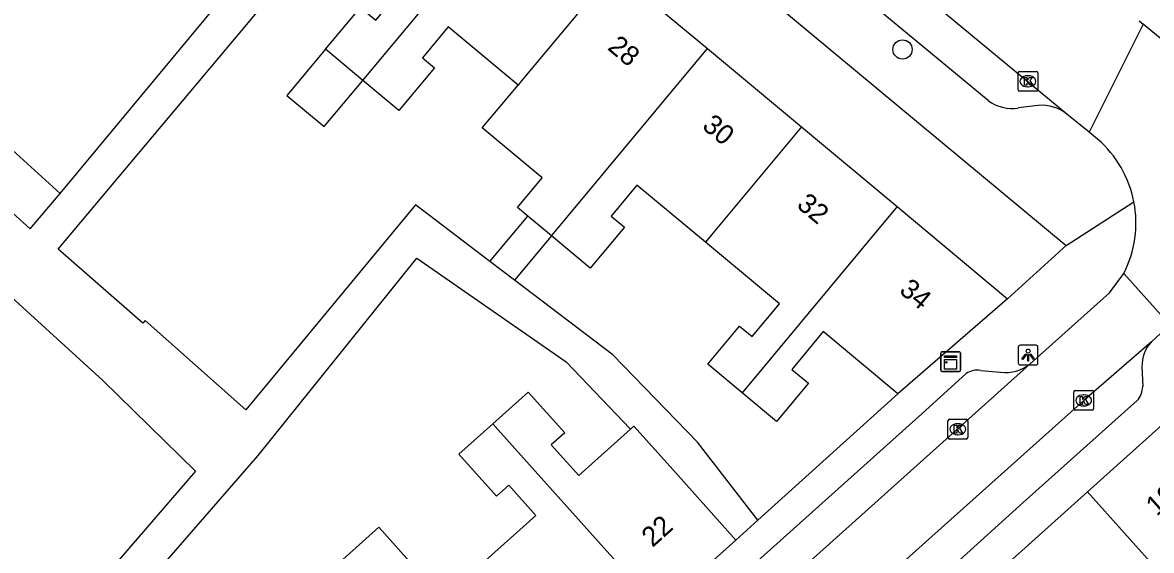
# Model space of a CAD drawing. Extents: x 158352 to 159489, y 383828 to 384597.
# Drawn here: x 159153.3 to 159210.4, y 384287.6 to 384314.3 of the extents above; entities that cross this region are included whole.
import ezdxf

# ---------------------------------------------------------------- set-up
doc = ezdxf.new("R2010")
doc.units = 0
for name, color, linetype in [('IMGEO_Boom', 7, 'Continuous'), ('IMGEO_Kast', 7, 'Continuous'), ('IMGEO_Kolk', 7, 'Continuous'), ('IMGEO_Lichtpunt', 7, 'Continuous'), ('IMGEO_Muur', 7, 'Continuous'), ('IMGEO_Pand', 7, 'Continuous'), ('IMGEO_Pand_nummerreeks', 7, 'Continuous'), ('IMGEO_Rijbaan_lokaal_open', 7, 'Continuous'), ('IMGEO_Voetpad_open', 7, 'Continuous')]:
    doc.layers.add(name, color=color, linetype=linetype)

msp = doc.modelspace()

# ---------------------------------------------------------------- linework, layer by layer
at = {"layer": 'IMGEO_Boom'}
msp.add_circle((159197.826, 384312.907), 0.489, dxfattribs=at)
at = {"layer": 'IMGEO_Kast'}
for p, q in [((159199.759, 384296.687), (159199.759, 384297.528)), ((159199.759, 384297.528), (159199.759, 384296.687)), ((159199.834, 384297.612), (159200.675, 384297.612)), ((159200.675, 384297.612), (159199.834, 384297.612)), ((159200.759, 384297.537), (159200.759, 384296.696)), ((159200.759, 384296.696), (159200.759, 384297.537)), ((159200.684, 384296.612), (159199.843, 384296.612)), ((159199.843, 384296.612), (159200.684, 384296.612))]:
    msp.add_line(p, q, dxfattribs=at)
for points in [[(159199.954, 384297.402), (159200.554, 384297.402), (159200.554, 384297.317), (159199.954, 384297.317), (159199.954, 384297.402)], [(159199.954, 384297.227), (159200.554, 384297.227), (159200.554, 384296.738), (159199.954, 384296.738), (159199.954, 384297.227)]]:
    msp.add_lwpolyline(points, dxfattribs=at)
msp.add_circle((159200.038, 384297.076), 0.0377, dxfattribs=at)
for centre, start, end in [((159199.837, 384297.534), 92.4484, 184.2845), ((159199.837, 384297.534), 92.4484, 184.2845), ((159200.681, 384297.534), 2.4484, 94.2845), ((159200.681, 384297.534), 2.4484, 94.2845), ((159199.837, 384296.69), 182.4484, 274.2845), ((159199.837, 384296.69), 182.4484, 274.2845), ((159200.681, 384296.69), 272.4484, 4.2845), ((159200.681, 384296.69), 272.4484, 4.2845)]:
    msp.add_arc(centre, 0.0779, start, end, dxfattribs=at)
at = {"layer": 'IMGEO_Kolk'}
for p, q in [((159203.67, 384310.871), (159203.67, 384311.723)), ((159203.745, 384311.797), (159204.597, 384311.797)), ((159204.158, 384311.577), (159204.183, 384311.577)), ((159204.671, 384311.723), (159204.671, 384310.871)), ((159204.181, 384311.017), (159204.156, 384311.017)), ((159204.597, 384310.797), (159203.745, 384310.797)), ((159206.492, 384294.726), (159206.492, 384295.578)), ((159206.567, 384295.652), (159207.419, 384295.652)), ((159207.493, 384295.578), (159207.493, 384294.726)), ((159206.98, 384295.432), (159207.005, 384295.432)), ((159207.419, 384294.652), (159206.567, 384294.652)), ((159207.003, 384294.872), (159206.978, 384294.872)), ((159200.122, 384293.269), (159200.122, 384294.121)), ((159200.197, 384294.195), (159201.049, 384294.195)), ((159200.61, 384293.975), (159200.635, 384293.975)), ((159201.123, 384294.121), (159201.123, 384293.269)), ((159201.049, 384293.195), (159200.197, 384293.195)), ((159200.633, 384293.415), (159200.608, 384293.415))]:
    msp.add_line(p, q, dxfattribs=at)
for points in [[(159203.67, 384310.871), (159203.67, 384311.723)], [(159203.745, 384311.797), (159204.597, 384311.797)], [(159203.991, 384311.497), (159204.114, 384311.497), (159204.114, 384311.346), (159204.244, 384311.497), (159204.408, 384311.497), (159204.262, 384311.346), (159204.415, 384311.097), (159204.263, 384311.097), (159204.178, 384311.261), (159204.114, 384311.194), (159204.114, 384311.097), (159203.991, 384311.097), (159203.991, 384311.497)], [(159204.671, 384311.723), (159204.671, 384310.871)], [(159204.597, 384310.797), (159203.745, 384310.797)], [(159206.492, 384294.726), (159206.492, 384295.578)], [(159206.567, 384295.652), (159207.419, 384295.652)], [(159207.493, 384295.578), (159207.493, 384294.726)], [(159206.813, 384295.352), (159206.936, 384295.352), (159206.936, 384295.201), (159207.066, 384295.352), (159207.23, 384295.352), (159207.084, 384295.201), (159207.237, 384294.952), (159207.085, 384294.952), (159207, 384295.116), (159206.936, 384295.049), (159206.936, 384294.952), (159206.813, 384294.952), (159206.813, 384295.352)], [(159207.419, 384294.652), (159206.567, 384294.652)], [(159200.122, 384293.269), (159200.122, 384294.121)], [(159200.197, 384294.195), (159201.049, 384294.195)], [(159200.443, 384293.895), (159200.566, 384293.895), (159200.566, 384293.744), (159200.696, 384293.895), (159200.86, 384293.895), (159200.714, 384293.744), (159200.867, 384293.495), (159200.715, 384293.495), (159200.63, 384293.659), (159200.566, 384293.592), (159200.566, 384293.495), (159200.443, 384293.495), (159200.443, 384293.895)], [(159201.123, 384294.121), (159201.123, 384293.269)], [(159201.049, 384293.195), (159200.197, 384293.195)]]:
    msp.add_lwpolyline(points, dxfattribs=at)
for centre, start, end in [((159203.747, 384311.721), 91.552, 178.448), ((159203.747, 384311.721), 91.552, 178.448), ((159204.595, 384311.721), 1.552, 88.448), ((159204.595, 384311.721), 1.552, 88.448), ((159203.747, 384310.873), 181.552, 268.448), ((159203.747, 384310.873), 181.552, 268.448), ((159204.595, 384310.873), 271.552, 358.448), ((159204.595, 384310.873), 271.552, 358.448), ((159206.569, 384295.576), 91.552, 178.448), ((159206.569, 384295.576), 91.552, 178.448), ((159207.417, 384295.576), 1.552, 88.448), ((159207.417, 384295.576), 1.552, 88.448), ((159206.569, 384294.728), 181.552, 268.448), ((159206.569, 384294.728), 181.552, 268.448), ((159207.417, 384294.728), 271.552, 358.448), ((159207.417, 384294.728), 271.552, 358.448), ((159200.199, 384294.119), 91.552, 178.448), ((159200.199, 384294.119), 91.552, 178.448), ((159201.047, 384294.119), 1.552, 88.448), ((159201.047, 384294.119), 1.552, 88.448), ((159200.199, 384293.271), 181.552, 268.448), ((159200.199, 384293.271), 181.552, 268.448), ((159201.047, 384293.271), 271.552, 358.448), ((159201.047, 384293.271), 271.552, 358.448)]:
    msp.add_arc(centre, 0.0765, start, end, dxfattribs=at)
for centre, major_axis, ratio, start_param, end_param in [((159204.157, 384311.297), (-0.387, 0.002), 0.722429, 4.712389, 7.853982), ((159204.182, 384311.297), (-0.39, 0.002), 0.717154, 1.570796, 4.712389), ((159206.979, 384295.152), (-0.387, 0.002), 0.722429, 4.712389, 7.853982), ((159207.004, 384295.152), (-0.39, 0.002), 0.717154, 1.570796, 4.712389), ((159200.609, 384293.695), (-0.387, 0.002), 0.722429, 4.712389, 7.853982), ((159200.634, 384293.695), (-0.39, 0.002), 0.717154, 1.570796, 4.712389)]:
    msp.add_ellipse(centre, major_axis=major_axis, ratio=ratio, start_param=start_param, end_param=end_param, dxfattribs=at)
at = {"layer": 'IMGEO_Lichtpunt'}
for p, q in [((159203.684, 384297.851), (159203.684, 384297.044)), ((159203.684, 384297.851), (159203.684, 384297.044)), ((159204.586, 384297.946), (159203.778, 384297.946)), ((159204.586, 384297.946), (159203.778, 384297.946)), ((159204.68, 384297.044), (159204.68, 384297.851)), ((159204.68, 384297.044), (159204.68, 384297.851)), ((159203.778, 384296.95), (159204.586, 384296.95)), ((159203.778, 384296.95), (159204.586, 384296.95))]:
    msp.add_line(p, q, dxfattribs=at)
for points in [[(159204.058, 384297.515), (159204.097, 384297.487), (159203.909, 384297.225), (159203.871, 384297.252), (159204.058, 384297.515)], [(159204.16, 384297.467), (159204.207, 384297.467), (159204.207, 384297.145), (159204.16, 384297.145), (159204.16, 384297.467)], [(159204.27, 384297.487), (159204.308, 384297.514), (159204.495, 384297.252), (159204.456, 384297.224), (159204.27, 384297.487)]]:
    msp.add_lwpolyline(points, dxfattribs=at)
msp.add_circle((159204.183, 384297.649), 0.0994, dxfattribs=at)
for centre, start, end in [((159203.778, 384297.851), 90, 180), ((159203.778, 384297.851), 90, 180), ((159204.586, 384297.851), 0, 90), ((159204.586, 384297.851), 0, 90), ((159203.778, 384297.044), 180, 270), ((159203.778, 384297.044), 180, 270), ((159204.586, 384297.044), 270, 0), ((159204.586, 384297.044), 270, 360)]:
    msp.add_arc(centre, 0.0946, start, end, dxfattribs=at)
at = {"layer": 'IMGEO_Muur'}
msp.add_lwpolyline([(159190.512, 384289.089), (159197.594, 384295.481)], dxfattribs=at)
at = {"layer": 'IMGEO_Pand'}
for points in [[(159170.516, 384311.346), (159170.584, 384311.428), (159178.46, 384320.872)], [(159168.63, 384312.919), (159170.397, 384315.039), (159171.182, 384314.384), (159172.535, 384316.006), (159168.795, 384319.124)], [(159183.209, 384316.912), (159178.531, 384311.302), (159178.37, 384311.109)], [(159183.209, 384316.912), (159187.959, 384312.952)], [(159178.37, 384311.109), (159174.841, 384314.052), (159173.529, 384312.479), (159174.137, 384311.972), (159172.344, 384309.822), (159170.516, 384311.346)], [(159168.63, 384312.919), (159166.676, 384310.574), (159168.554, 384309.008), (159170.516, 384311.346)], [(159170.516, 384311.346), (159168.63, 384312.919)], [(159180.057, 384303.476), (159180.158, 384303.598), (159187.959, 384312.952)], [(159187.959, 384312.952), (159192.708, 384308.992)], [(159178.858, 384304.475), (159178.343, 384304.905), (159179.599, 384306.411), (159176.563, 384308.942), (159178.37, 384311.109)], [(159155.206, 384305.626), (159150.73, 384309.667), (159149.226, 384307.855)], [(159192.708, 384308.992), (159188.159, 384303.537), (159187.848, 384303.164)], [(159192.708, 384308.992), (159197.549, 384304.956)], [(159149.226, 384307.855), (159153.686, 384303.826), (159155.206, 384305.626)], [(159187.848, 384303.164), (159184.386, 384306.05), (159183.076, 384304.479), (159183.753, 384303.914), (159182.022, 384301.838), (159180.057, 384303.476)], [(159197.549, 384304.956), (159195.633, 384302.653), (159189.71, 384295.535)], [(159197.549, 384304.956), (159203.136, 384300.297)], [(159176.948, 384302.184), (159178.858, 384304.475)], [(159180.057, 384303.476), (159178.858, 384304.475)], [(159180.057, 384303.476), (159178.199, 384301.232)], [(159189.71, 384295.535), (159187.967, 384296.989), (159189.573, 384298.914), (159190.215, 384298.38), (159191.598, 384300.037), (159187.848, 384303.164)], [(159178.199, 384301.232), (159176.948, 384302.184)], [(159203.136, 384300.297), (159197.594, 384295.481)], [(159197.594, 384295.481), (159193.815, 384298.632), (159192.221, 384296.72), (159193.066, 384296.016), (159191.453, 384294.081), (159189.71, 384295.535)], [(159177.089, 384293.971), (159178.877, 384295.573), (159180.73, 384293.504), (159180.055, 384292.9), (159181.448, 384291.346), (159184.067, 384293.692)], [(159176.554, 384286.898), (159179.271, 384289.332), (159177.901, 384290.861), (159177.275, 384290.3), (159175.368, 384292.429), (159177.089, 384293.971)], [(159177.089, 384293.971), (159177.343, 384293.688), (159185.498, 384284.588)], [(159184.067, 384293.692), (159184.238, 384293.845), (159186.062, 384291.808), (159189.399, 384288.084)], [(159210.968, 384293.911), (159207.182, 384290.519)], [(159203.366, 384287.1), (159207.182, 384290.519)], [(159207.182, 384290.519), (159214.674, 384282.155)], [(159169.5, 384287.098), (159171.326, 384288.734), (159173.171, 384286.674), (159172.499, 384286.072), (159173.894, 384284.515), (159176.554, 384286.898)], [(159189.399, 384288.084), (159185.498, 384284.588)]]:
    msp.add_lwpolyline(points, dxfattribs=at)
at = {"layer": 'IMGEO_Rijbaan_lokaal_open'}
for points in [[(159206.145, 384309.643), (159182.845, 384328.912)], [(159209.805, 384314.35), (159210.002, 384314.188)], [(159210.002, 384314.188), (159207.264, 384308.732)], [(159211.544, 384312.921), (159210.002, 384314.188)], [(159207.264, 384308.732), (159206.145, 384309.643)], [(159207.698, 384308.37), (159207.264, 384308.732)], [(159204.28, 384296.997), (159208.298, 384300.6), (159209.022, 384301.576)], [(159209.022, 384301.576), (159211.356, 384298.969)], [(159211.356, 384298.969), (159210.418, 384298.12)], [(159210.418, 384298.12), (159206.993, 384295.153), (159190.807, 384280.663)], [(159188.728, 384283.052), (159204.28, 384296.997)]]:
    msp.add_lwpolyline(points, dxfattribs=at)
for centre, radius, start, end in [((159204.038, 384304.131), 5.6, 11.0235, 49.1921), ((159204.033, 384304.131), 5.605, 332.8799, 11.0148)]:
    msp.add_arc(centre, radius, start, end, dxfattribs=at)
at = {"layer": 'IMGEO_Voetpad_open'}
for points in [[(159176.116, 384327.914), (159206.109, 384302.993)], [(159202.164, 384310.319), (159194.878, 384316.358), (159184.589, 384324.835)], [(159155.206, 384305.626), (159167.387, 384320.29)], [(159176.948, 384302.184), (159173.19, 384305.045), (159164.589, 384294.676), (159159.509, 384299.196), (159159.389, 384299.061), (159155.1, 384302.796), (159168.795, 384319.124)], [(159204.694, 384310.079), (159203.685, 384309.947)], [(159206.109, 384302.993), (159209.535, 384305.202)], [(159132.249, 384287.558), (159149.628, 384303.199), (159157.36, 384296.152), (159162.054, 384291.576), (159154.04, 384282.284), (159152.116, 384280.413), (159156.255, 384275.749), (159156.404, 384275.881), (159164.986, 384266.22)], [(159206.109, 384302.993), (159203.136, 384300.297)], [(159161.312, 384273.043), (159154.77, 384280.345), (159165.213, 384292.356), (159173.245, 384302.352), (159180.81, 384297.099), (159184.067, 384293.692)], [(159190.512, 384289.089), (159187.453, 384293.046), (159183.163, 384297.453), (159178.199, 384301.232)], [(159201.781, 384296.671), (159202.792, 384296.589)], [(159209.942, 384296.851), (159209.979, 384295.857)], [(159189.361, 384286.012), (159198.802, 384294.468), (159201.05, 384296.506)], [(159197.594, 384295.481), (159190.512, 384289.089)], [(159209.697, 384295.139), (159203.931, 384289.985), (159194.089, 384281.089)], [(159189.399, 384288.084), (159190.512, 384289.089)]]:
    msp.add_lwpolyline(points, dxfattribs=at)
for centre, radius, start, end in [((159203.375, 384311.974), 2.051, 233.8106, 278.7027), ((159204.858, 384307.992), 2.093, 52.0562, 94.4946), ((159211.753, 384296.895), 1.812, 137.4764, 181.4016), ((159201.625, 384295.662), 1.021, 81.1991, 124.2399), ((159203.071, 384298.488), 1.92, 261.6406, 309.0259), ((159208.908, 384295.863), 1.071, 317.4473, 359.6671)]:
    msp.add_arc(centre, radius, start, end, dxfattribs=at)

# ---------------------------------------------------------------- texts
at = {"layer": 'IMGEO_Pand_nummerreeks'}
for s, rotation, p in [('28', 320.1737, (159182.85, 384312.94)), ('30', 320.1758, (159187.636, 384308.949)), ('32', 320.1758, (159192.418, 384304.962)), ('34', 320.1864, (159197.607, 384300.635)), ('19', 41.8603, (159210.695, 384289.262)), ('22', 41.8603, (159185.179, 384287.686))]:
    msp.add_text(s, height=1, rotation=rotation, dxfattribs=at).set_placement(p)

doc.saveas('drawing.dxf')
